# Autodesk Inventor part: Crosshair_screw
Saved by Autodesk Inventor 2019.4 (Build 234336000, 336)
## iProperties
Created: 2019-10
Part Number: Crosshair_screw
Material: Generic
Document SubType Name: Modeling
Designer: Administrator
Density: 1 g/cm^3
Appearance: Default
Title: Crosshair_screw
Author: Administrator
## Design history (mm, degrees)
feature "Body1"
body "Solid1"
